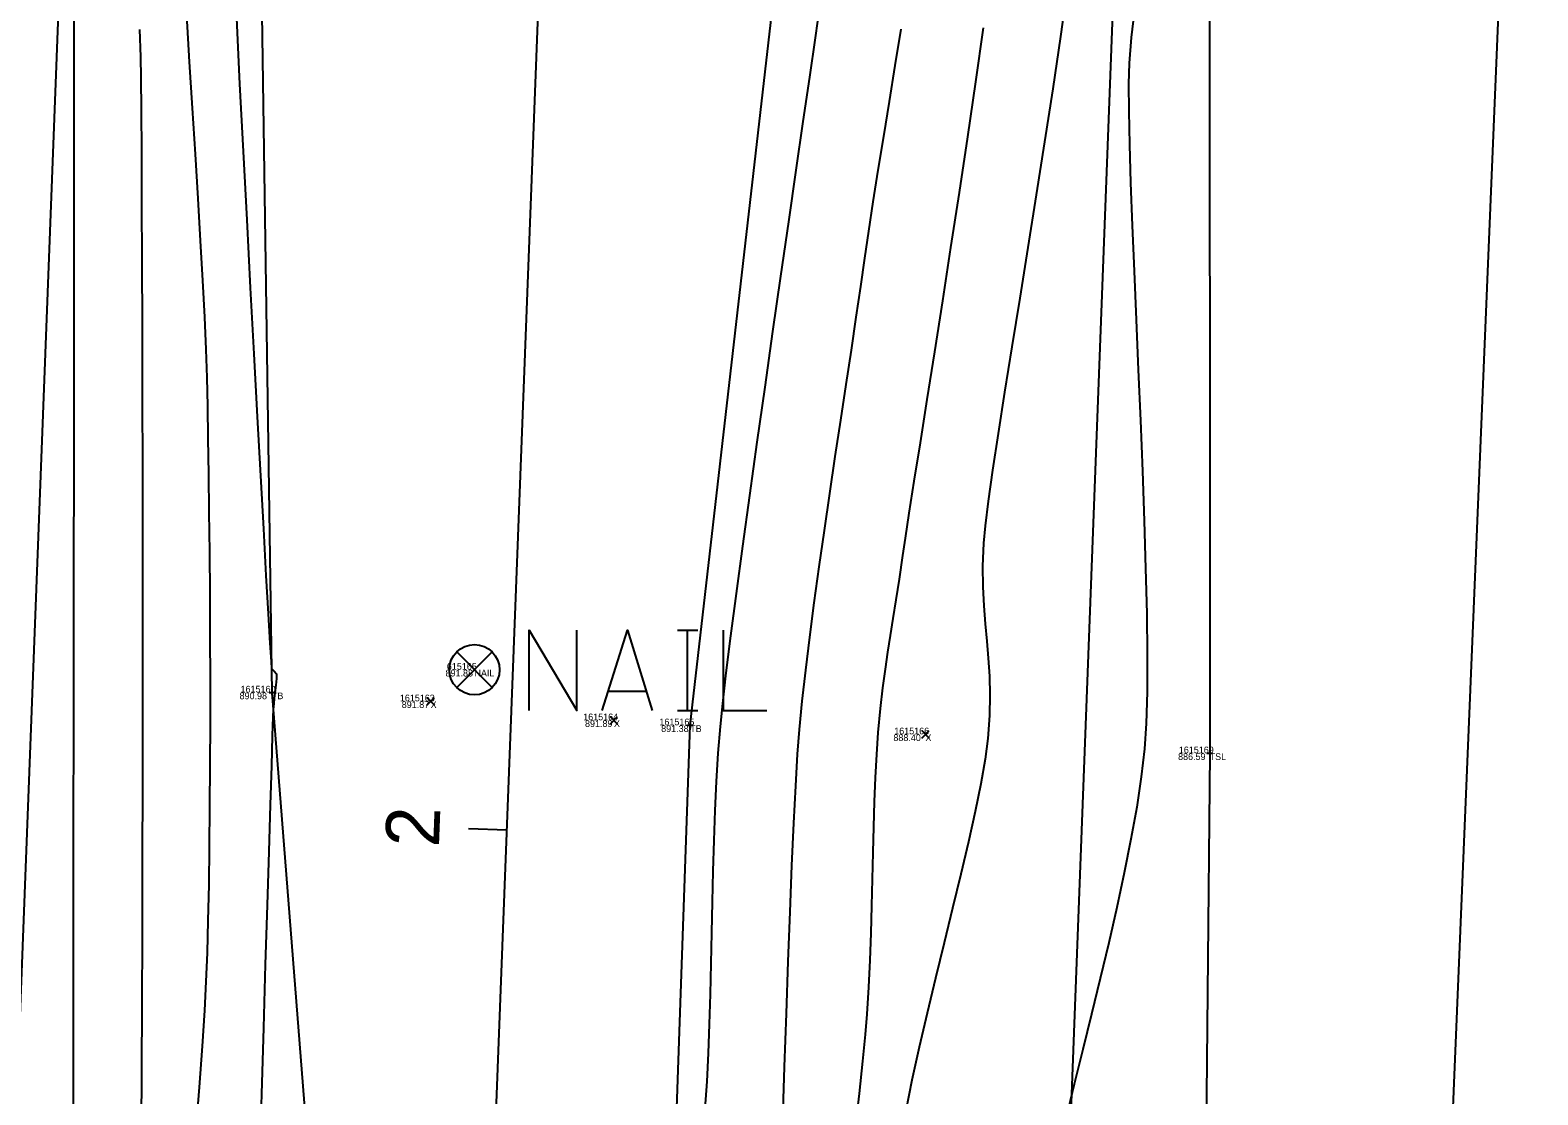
# Model space of a CAD drawing. Extents: x 1957117 to 1971063, y 701601 to 715861.
# Drawn here: x 1962680.5 to 1962759.2, y 702184.3 to 702239.9 of the extents above; entities that cross this region are included whole.
import ezdxf

# ---------------------------------------------------------------- set-up
doc = ezdxf.new("R2010")
doc.units = 0
for name, color, linetype in [('AP_X_Lights', 7, 'Continuous'), ('DT_X_Break_Line', 7, 'Continuous'), ('DT_X_Contour_Major', 7, 'Continuous'), ('DT_X_Contour_Minor', 7, 'Continuous'), ('DT_X_TIN_Hull', 7, 'Continuous'), ('GE_X_CL_20', 7, 'Continuous'), ('PV_P_Drive', 7, 'Continuous'), ('PV_P_Shoulder', 7, 'Continuous'), ('RS_Raster1', 7, 'Continuous'), ('RW_X_Esmt_RR', 7, 'Continuous'), ('SC_Scratch1', 7, 'Continuous'), ('SC_Shading2', 7, 'Continuous')]:
    doc.layers.add(name, color=color, linetype=linetype)

msp = doc.modelspace()

# ---------------------------------------------------------------- linework, layer by layer
at = {"layer": 'AP_X_Lights'}
for p, q in [((1962701.194, 702204.663), (1962701.582, 702205.053)), ((1962701.194, 702205.053), (1962701.582, 702204.663)), ((1962710.763, 702203.674), (1962711.151, 702204.064)), ((1962710.763, 702204.064), (1962711.151, 702203.674)), ((1962727.023, 702202.939), (1962727.411, 702203.329)), ((1962727.023, 702203.329), (1962727.411, 702202.939))]:
    msp.add_line(p, q, dxfattribs=at)
at = {"layer": 'DT_X_Break_Line'}
for points in [[(1962712.212, 702702.955), (1962716.271, 702654.75), (1962711.053, 702609.737), (1962713.646, 702554.428), (1962708.781, 702505.283), (1962707.233, 702455.469), (1962704.944, 702406.927), (1962695.192, 702355.079), (1962699.519, 702306.049), (1962692.358, 702256.103), (1962693.103, 702205.318), (1962697.09, 702154.707), (1962695.369, 702143.214), (1962687.557, 702105.709), (1962680.996, 702055.861)], [(1962752.132, 702702.919), (1962747.065, 702649.147), (1962745.48, 702606.97), (1962743.008, 702552.829), (1962740.623, 702503.302), (1962740.641, 702452.933), (1962736.982, 702403.388), (1962741.529, 702352.919), (1962733.397, 702302.963), (1962742.046, 702251.987), (1962742.053, 702202.145), (1962741.582, 702152.179), (1962738.197, 702102.408), (1962725.619, 702053.061)], [(1962713.582, 702053.996), (1962711.466, 702104.13), (1962714.937, 702203.608), (1962720.713, 702253.951), (1962719.889, 702303.145), (1962721.566, 702358.521), (1962719.193, 702407.367), (1962722.415, 702453.828), (1962727.642, 702504.653), (1962726.923, 702553.596), (1962728.43, 702603.611), (1962735.623, 702653.941), (1962730.179, 702698.673)]]:
    msp.add_lwpolyline(points, dxfattribs=at)
at = {"layer": 'DT_X_Contour_Major'}
for points in [[(1962688.638, 702240.683), (1962688.788, 702238.252), (1962688.94, 702235.823), (1962689.089, 702233.432), (1962689.232, 702231.112), (1962689.364, 702228.896), (1962689.48, 702226.821), (1962689.578, 702224.919), (1962689.652, 702223.224), (1962689.7, 702221.771), (1962689.733, 702220.265), (1962689.764, 702218.573), (1962689.792, 702216.721), (1962689.817, 702214.736), (1962689.838, 702212.644), (1962689.855, 702210.471), (1962689.867, 702208.246), (1962689.873, 702205.994), (1962689.873, 702203.743), (1962689.867, 702201.518), (1962689.854, 702199.346), (1962689.833, 702197.255), (1962689.804, 702195.27), (1962689.767, 702193.419), (1962689.72, 702191.729), (1962689.663, 702190.225), (1962689.582, 702188.714), (1962689.459, 702186.858), (1962689.299, 702184.713), (1962689.11, 702182.335)], [(1962688.638, 702240.683), (1962688.788, 702238.252), (1962688.94, 702235.823), (1962689.089, 702233.432), (1962689.232, 702231.112), (1962689.364, 702228.896), (1962689.48, 702226.821), (1962689.578, 702224.919), (1962689.652, 702223.224), (1962689.7, 702221.771), (1962689.733, 702220.265), (1962689.764, 702218.573), (1962689.792, 702216.721), (1962689.817, 702214.736), (1962689.838, 702212.644), (1962689.855, 702210.471), (1962689.867, 702208.246), (1962689.873, 702205.994), (1962689.873, 702203.743), (1962689.867, 702201.518), (1962689.854, 702199.346), (1962689.833, 702197.255), (1962689.804, 702195.27), (1962689.767, 702193.419), (1962689.72, 702191.729), (1962689.663, 702190.225), (1962689.582, 702188.714), (1962689.459, 702186.858), (1962689.299, 702184.713), (1962689.11, 702182.335)], [(1962725.93, 702239.956), (1962725.625, 702238.053), (1962725.319, 702236.175), (1962725.021, 702234.348), (1962724.737, 702232.593), (1962724.473, 702230.934), (1962724.236, 702229.395), (1962724.035, 702227.999), (1962723.825, 702226.518), (1962723.589, 702224.91), (1962723.334, 702223.196), (1962723.063, 702221.398), (1962722.782, 702219.536), (1962722.495, 702217.631), (1962722.209, 702215.705), (1962721.927, 702213.778), (1962721.656, 702211.872), (1962721.399, 702210.007), (1962721.163, 702208.206), (1962720.952, 702206.488), (1962720.772, 702204.875), (1962720.627, 702203.388), (1962720.528, 702202.095), (1962720.429, 702200.448), (1962720.33, 702198.496), (1962720.232, 702196.286), (1962720.133, 702193.862), (1962720.036, 702191.273), (1962719.94, 702188.565), (1962719.846, 702185.785), (1962719.754, 702182.979)], [(1962725.93, 702239.956), (1962725.625, 702238.053), (1962725.319, 702236.175), (1962725.021, 702234.348), (1962724.737, 702232.593), (1962724.473, 702230.934), (1962724.236, 702229.395), (1962724.035, 702227.999), (1962723.825, 702226.518), (1962723.589, 702224.91), (1962723.334, 702223.196), (1962723.063, 702221.398), (1962722.782, 702219.536), (1962722.495, 702217.631), (1962722.209, 702215.705), (1962721.927, 702213.778), (1962721.656, 702211.872), (1962721.399, 702210.007), (1962721.163, 702208.206), (1962720.952, 702206.488), (1962720.772, 702204.875), (1962720.627, 702203.388), (1962720.528, 702202.095), (1962720.429, 702200.448), (1962720.33, 702198.496), (1962720.232, 702196.286), (1962720.133, 702193.862), (1962720.036, 702191.273), (1962719.94, 702188.565), (1962719.846, 702185.785), (1962719.754, 702182.979)]]:
    msp.add_lwpolyline(points, dxfattribs=at)
at = {"layer": 'DT_X_Contour_Minor'}
for points in [[(1962734.639, 702242.203), (1962734.264, 702239.567), (1962733.86, 702236.842), (1962733.435, 702234.07), (1962732.999, 702231.295), (1962732.563, 702228.557), (1962732.136, 702225.9), (1962731.729, 702223.366), (1962731.351, 702220.997), (1962731.012, 702218.836), (1962730.722, 702216.924), (1962730.491, 702215.304), (1962730.329, 702214.019), (1962730.245, 702213.11), (1962730.203, 702211.909), (1962730.214, 702210.827), (1962730.263, 702209.835), (1962730.337, 702208.904), (1962730.42, 702208.003), (1962730.498, 702207.103), (1962730.557, 702206.174), (1962730.582, 702205.186), (1962730.559, 702204.111), (1962730.474, 702202.917), (1962730.334, 702201.837), (1962730.109, 702200.558), (1962729.814, 702199.112), (1962729.461, 702197.527), (1962729.064, 702195.834), (1962728.637, 702194.063), (1962728.192, 702192.244), (1962727.744, 702190.406), (1962727.306, 702188.581), (1962726.891, 702186.796), (1962726.513, 702185.084), (1962726.186, 702183.473)], [(1962734.639, 702242.203), (1962734.264, 702239.567), (1962733.86, 702236.842), (1962733.435, 702234.07), (1962732.999, 702231.295), (1962732.563, 702228.557), (1962732.136, 702225.9), (1962731.729, 702223.366), (1962731.351, 702220.997), (1962731.012, 702218.836), (1962730.722, 702216.924), (1962730.491, 702215.304), (1962730.329, 702214.019), (1962730.245, 702213.11), (1962730.203, 702211.909), (1962730.214, 702210.827), (1962730.263, 702209.835), (1962730.337, 702208.904), (1962730.42, 702208.003), (1962730.498, 702207.103), (1962730.557, 702206.174), (1962730.582, 702205.186), (1962730.559, 702204.111), (1962730.474, 702202.917), (1962730.334, 702201.837), (1962730.109, 702200.558), (1962729.814, 702199.112), (1962729.461, 702197.527), (1962729.064, 702195.834), (1962728.637, 702194.063), (1962728.192, 702192.244), (1962727.744, 702190.406), (1962727.306, 702188.581), (1962726.891, 702186.796), (1962726.513, 702185.084), (1962726.186, 702183.473)], [(1962682.772, 702241.561), (1962682.769, 702236.335), (1962682.765, 702230.56), (1962682.761, 702224.357), (1962682.756, 702217.845), (1962682.75, 702211.146), (1962682.744, 702204.38), (1962682.738, 702197.667), (1962682.731, 702191.128), (1962682.724, 702184.883), (1962682.716, 702179.052)], [(1962682.772, 702241.561), (1962682.769, 702236.335), (1962682.765, 702230.56), (1962682.761, 702224.357), (1962682.756, 702217.845), (1962682.75, 702211.146), (1962682.744, 702204.38), (1962682.738, 702197.667), (1962682.731, 702191.128), (1962682.724, 702184.883), (1962682.716, 702179.052)], [(1962715.725, 702183.61), (1962715.816, 702185.016), (1962715.889, 702186.486), (1962715.947, 702188.008), (1962715.994, 702189.572), (1962716.033, 702191.165), (1962716.069, 702192.775), (1962716.104, 702194.39), (1962716.143, 702196), (1962716.188, 702197.592), (1962716.245, 702199.154), (1962716.315, 702200.675), (1962716.403, 702202.144), (1962716.513, 702203.547), (1962716.635, 702204.747), (1962716.822, 702206.339), (1962717.065, 702208.272), (1962717.356, 702210.494), (1962717.687, 702212.955), (1962718.051, 702215.603), (1962718.44, 702218.389), (1962718.844, 702221.261), (1962719.258, 702224.168), (1962719.672, 702227.06), (1962720.078, 702229.885), (1962720.469, 702232.592), (1962720.837, 702235.131), (1962721.174, 702237.451), (1962721.471, 702239.501), (1962721.721, 702241.23)], [(1962715.725, 702183.61), (1962715.816, 702185.016), (1962715.889, 702186.486), (1962715.947, 702188.008), (1962715.994, 702189.572), (1962716.033, 702191.165), (1962716.069, 702192.775), (1962716.104, 702194.39), (1962716.143, 702196), (1962716.188, 702197.592), (1962716.245, 702199.154), (1962716.315, 702200.675), (1962716.403, 702202.144), (1962716.513, 702203.547), (1962716.635, 702204.747), (1962716.822, 702206.339), (1962717.065, 702208.272), (1962717.356, 702210.494), (1962717.687, 702212.955), (1962718.051, 702215.603), (1962718.44, 702218.389), (1962718.844, 702221.261), (1962719.258, 702224.168), (1962719.672, 702227.06), (1962720.078, 702229.885), (1962720.469, 702232.592), (1962720.837, 702235.131), (1962721.174, 702237.451), (1962721.471, 702239.501), (1962721.721, 702241.23)], [(1962691.248, 702240.531), (1962691.42, 702237.102), (1962691.601, 702233.569), (1962691.787, 702229.997), (1962691.974, 702226.453), (1962692.159, 702223.001), (1962692.337, 702219.707), (1962692.505, 702216.637), (1962692.659, 702213.855), (1962692.795, 702211.429), (1962692.909, 702209.423), (1962692.998, 702207.902), (1962693.058, 702206.933), (1962693.084, 702206.58), (1962693.213, 702206.435), (1962693.335, 702206.29), (1962693.345, 702206.055), (1962693.306, 702205.702), (1962693.261, 702205.309), (1962693.228, 702204.998), (1962693.199, 702204.751), (1962693.172, 702204.44), (1962693.158, 702204.052), (1962693.125, 702203.049), (1962693.076, 702201.497), (1962693.012, 702199.462), (1962692.936, 702197.011), (1962692.85, 702194.209), (1962692.758, 702191.124), (1962692.66, 702187.82), (1962692.56, 702184.365), (1962692.459, 702180.824)], [(1962691.248, 702240.531), (1962691.42, 702237.102), (1962691.601, 702233.569), (1962691.787, 702229.997), (1962691.974, 702226.453), (1962692.159, 702223.001), (1962692.337, 702219.707), (1962692.505, 702216.637), (1962692.659, 702213.855), (1962692.795, 702211.429), (1962692.909, 702209.423), (1962692.998, 702207.902), (1962693.058, 702206.933), (1962693.084, 702206.58), (1962693.213, 702206.435), (1962693.335, 702206.29), (1962693.345, 702206.055), (1962693.306, 702205.702), (1962693.261, 702205.309), (1962693.228, 702204.998), (1962693.199, 702204.751), (1962693.172, 702204.44), (1962693.158, 702204.052), (1962693.125, 702203.049), (1962693.076, 702201.497), (1962693.012, 702199.462), (1962692.936, 702197.011), (1962692.85, 702194.209), (1962692.758, 702191.124), (1962692.66, 702187.82), (1962692.56, 702184.365), (1962692.459, 702180.824)], [(1962738.119, 702240.816), (1962737.961, 702239.515), (1962737.854, 702238.176), (1962737.823, 702237.102), (1962737.828, 702235.673), (1962737.865, 702233.934), (1962737.927, 702231.929), (1962738.01, 702229.706), (1962738.107, 702227.307), (1962738.215, 702224.78), (1962738.327, 702222.169), (1962738.438, 702219.52), (1962738.542, 702216.877), (1962738.636, 702214.286), (1962738.712, 702211.793), (1962738.767, 702209.442), (1962738.794, 702207.28), (1962738.788, 702205.35), (1962738.744, 702203.699), (1962738.657, 702202.371), (1962738.485, 702200.91), (1962738.244, 702199.332), (1962737.945, 702197.659), (1962737.595, 702195.908), (1962737.205, 702194.1), (1962736.785, 702192.254), (1962736.343, 702190.389), (1962735.89, 702188.526), (1962735.434, 702186.683), (1962734.986, 702184.88), (1962734.554, 702183.137)], [(1962738.119, 702240.816), (1962737.961, 702239.515), (1962737.854, 702238.176), (1962737.823, 702237.102), (1962737.828, 702235.673), (1962737.865, 702233.934), (1962737.927, 702231.929), (1962738.01, 702229.706), (1962738.107, 702227.307), (1962738.215, 702224.78), (1962738.327, 702222.169), (1962738.438, 702219.52), (1962738.542, 702216.877), (1962738.636, 702214.286), (1962738.712, 702211.793), (1962738.767, 702209.442), (1962738.794, 702207.28), (1962738.788, 702205.35), (1962738.744, 702203.699), (1962738.657, 702202.371), (1962738.485, 702200.91), (1962738.244, 702199.332), (1962737.945, 702197.659), (1962737.595, 702195.908), (1962737.205, 702194.1), (1962736.785, 702192.254), (1962736.343, 702190.389), (1962735.89, 702188.526), (1962735.434, 702186.683), (1962734.986, 702184.88), (1962734.554, 702183.137)], [(1962686.189, 702239.926), (1962686.238, 702238.508), (1962686.256, 702237.401), (1962686.274, 702235.718), (1962686.29, 702233.522), (1962686.304, 702230.872), (1962686.317, 702227.829), (1962686.327, 702224.452), (1962686.336, 702220.803), (1962686.342, 702216.942), (1962686.346, 702212.928), (1962686.347, 702208.823), (1962686.346, 702204.686), (1962686.342, 702200.579), (1962686.336, 702196.561), (1962686.326, 702192.692), (1962686.313, 702189.033), (1962686.297, 702185.645), (1962686.278, 702182.587)], [(1962686.189, 702239.926), (1962686.238, 702238.508), (1962686.256, 702237.401), (1962686.274, 702235.718), (1962686.29, 702233.522), (1962686.304, 702230.872), (1962686.317, 702227.829), (1962686.327, 702224.452), (1962686.336, 702220.803), (1962686.342, 702216.942), (1962686.346, 702212.928), (1962686.347, 702208.823), (1962686.346, 702204.686), (1962686.342, 702200.579), (1962686.336, 702196.561), (1962686.326, 702192.692), (1962686.313, 702189.033), (1962686.297, 702185.645), (1962686.278, 702182.587)], [(1962730.222, 702240.026), (1962729.824, 702237.205), (1962729.404, 702234.32), (1962728.97, 702231.42), (1962728.533, 702228.551), (1962728.102, 702225.762), (1962727.685, 702223.101), (1962727.293, 702220.614), (1962726.934, 702218.35), (1962726.619, 702216.357), (1962726.355, 702214.682), (1962726.153, 702213.373), (1962726.021, 702212.478), (1962725.842, 702211.231), (1962725.676, 702210.15), (1962725.521, 702209.187), (1962725.375, 702208.295), (1962725.239, 702207.426), (1962725.108, 702206.532), (1962724.983, 702205.566), (1962724.861, 702204.481), (1962724.74, 702203.23), (1962724.654, 702202.089), (1962724.589, 702200.882), (1962724.54, 702199.619), (1962724.502, 702198.309), (1962724.47, 702196.959), (1962724.441, 702195.579), (1962724.409, 702194.178), (1962724.37, 702192.763), (1962724.318, 702191.345), (1962724.25, 702189.932), (1962724.16, 702188.532), (1962724.068, 702187.46), (1962723.93, 702186.067), (1962723.75, 702184.393), (1962723.536, 702182.477)], [(1962730.222, 702240.026), (1962729.824, 702237.205), (1962729.404, 702234.32), (1962728.97, 702231.42), (1962728.533, 702228.551), (1962728.102, 702225.762), (1962727.685, 702223.101), (1962727.293, 702220.614), (1962726.934, 702218.35), (1962726.619, 702216.357), (1962726.355, 702214.682), (1962726.153, 702213.373), (1962726.021, 702212.478), (1962725.842, 702211.231), (1962725.676, 702210.15), (1962725.521, 702209.187), (1962725.375, 702208.295), (1962725.239, 702207.426), (1962725.108, 702206.532), (1962724.983, 702205.566), (1962724.861, 702204.481), (1962724.74, 702203.23), (1962724.654, 702202.089), (1962724.589, 702200.882), (1962724.54, 702199.619), (1962724.502, 702198.309), (1962724.47, 702196.959), (1962724.441, 702195.579), (1962724.409, 702194.178), (1962724.37, 702192.763), (1962724.318, 702191.345), (1962724.25, 702189.932), (1962724.16, 702188.532), (1962724.068, 702187.46), (1962723.93, 702186.067), (1962723.75, 702184.393), (1962723.536, 702182.477)]]:
    msp.add_lwpolyline(points, dxfattribs=at)
at = {"layer": 'DT_X_TIN_Hull'}
msp.add_lwpolyline([(1962657.931, 702308.011), (1962655.854, 702258.355), (1962653.64, 702207.97), (1962651.503, 702157.712), (1962649.771, 702107.746), (1962674.688, 702087.643), (1962671.405, 702038.683), (1962651.95, 702019.751), (1962598.276, 702023.522), (1962596.236, 701997.877), (1962651.443, 701993.881), (1962750.651, 701987.35), (1962803.275, 701984.672), (1962804.883, 701997.219), (1962805.914, 702009.441), (1962753.632, 702013.572), (1962730.2, 702029.616), (1962722.307, 702088.916), (1962751.157, 702101.248), (1962753.404, 702150.955), (1962757.576, 702251.621), (1962759.026, 702351.713)], dxfattribs=at)
at = {"layer": 'GE_X_CL_20'}
msp.add_line((1962705.358, 702198.126), (1962703.359, 702198.203), dxfattribs=at)
msp.add_lwpolyline([(1962741.373, 703141.619), (1962697.729, 701998.272)], dxfattribs=at)
at = {"layer": 'PV_P_Drive'}
for p, q in [((1962692.957, 702205.318), (1962693.249, 702205.318)), ((1962693.103, 702205.464), (1962693.103, 702205.172)), ((1962693.103, 702205.318), (1962693.103, 702205.318)), ((1962714.791, 702203.608), (1962715.083, 702203.608)), ((1962714.937, 702203.754), (1962714.937, 702203.462)), ((1962714.937, 702203.608), (1962714.937, 702203.608)), ((1962741.907, 702202.145), (1962742.199, 702202.145)), ((1962742.053, 702202.291), (1962742.053, 702201.999)), ((1962742.053, 702202.145), (1962742.053, 702202.145))]:
    msp.add_line(p, q, dxfattribs=at)
at = {"layer": 'RW_X_Esmt_RR'}
for points in [[(1962674.265, 702039.003), (1962716.391, 703142.573)], [(1962729.176, 702035.621), (1962771.351, 703140.475)]]:
    msp.add_lwpolyline(points, dxfattribs=at)
at = {"layer": 'SC_Shading2'}
for p, q in [((1962702.749, 702207.434), (1962704.605, 702205.578)), ((1962702.749, 702205.578), (1962704.605, 702207.434))]:
    msp.add_line(p, q, dxfattribs=at)
for points in [[(1962706.537, 702204.381), (1962706.537, 702208.581), (1962709.017, 702204.381), (1962709.017, 702208.581)], [(1962710.34, 702204.381), (1962711.663, 702208.581), (1962712.952, 702204.381)], [(1962714.275, 702208.581), (1962715.333, 702208.581)], [(1962714.804, 702204.381), (1962714.804, 702208.581)], [(1962716.656, 702208.581), (1962716.656, 702204.381), (1962718.938, 702204.381)], [(1962712.622, 702205.373), (1962710.671, 702205.373)], [(1962714.275, 702204.381), (1962715.333, 702204.381)]]:
    msp.add_lwpolyline(points, dxfattribs=at)
msp.add_circle((1962703.677, 702206.506), 1.312, dxfattribs=at)

# ---------------------------------------------------------------- texts
at = {"layer": 'GE_X_CL_20'}
msp.add_text('2', height=2.8, rotation=87.81394, dxfattribs=at).set_placement((1962701.82, 702197.216))
at = {"layer": 'PV_P_Shoulder'}
for s, p in [('891.88', (1962702.167, 702206.156)), ('890.98', (1962691.416, 702204.968)), ('891.87', (1962699.881, 702204.508)), ('891.89', (1962709.447, 702203.519)), ('891.38', (1962713.422, 702203.258)), ('888.40', (1962725.544, 702202.784)), ('886.59', (1962740.405, 702201.795))]:
    msp.add_text(s, height=0.35, dxfattribs=at).set_placement(p)
at = {"layer": 'RS_Raster1'}
for s, p in [('615165', (1962702.236, 702206.506)), ('1615160', (1962691.467, 702205.318)), ('1615163', (1962699.782, 702204.858)), ('1615164', (1962709.354, 702203.869)), ('1615165', (1962713.331, 702203.608)), ('1615166', (1962725.589, 702203.134)), ('1615169', (1962740.444, 702202.145))]:
    msp.add_text(s, height=0.35, dxfattribs=at).set_placement(p)
at = {"layer": 'SC_Scratch1'}
for s, p in [('NAIL', (1962703.677, 702206.156)), ('TB', (1962693.103, 702204.968)), ('X', (1962701.388, 702204.508)), ('X', (1962710.957, 702203.519)), ('TB', (1962714.937, 702203.258)), ('X', (1962727.217, 702202.784)), ('TSL', (1962742.053, 702201.795))]:
    msp.add_text(s, height=0.35, dxfattribs=at).set_placement(p)

doc.saveas('drawing.dxf')
